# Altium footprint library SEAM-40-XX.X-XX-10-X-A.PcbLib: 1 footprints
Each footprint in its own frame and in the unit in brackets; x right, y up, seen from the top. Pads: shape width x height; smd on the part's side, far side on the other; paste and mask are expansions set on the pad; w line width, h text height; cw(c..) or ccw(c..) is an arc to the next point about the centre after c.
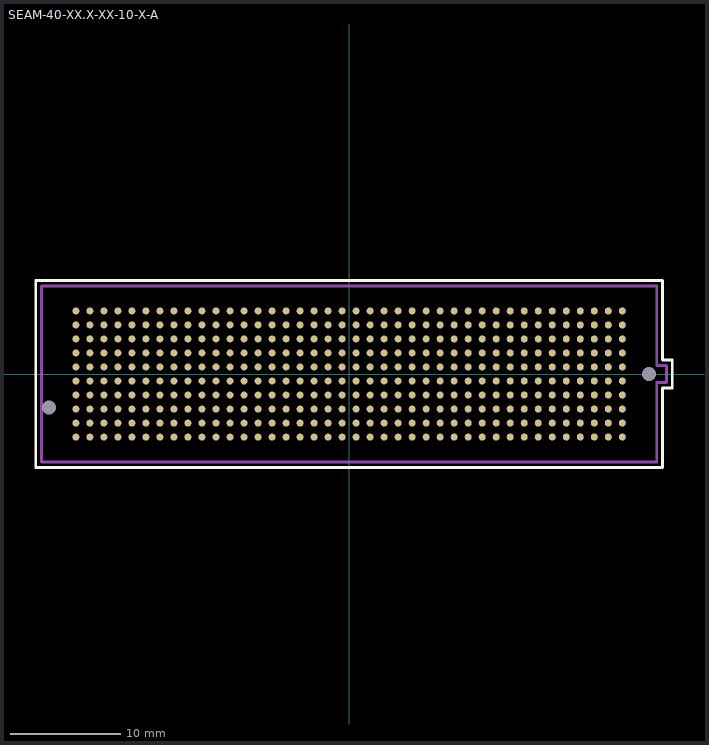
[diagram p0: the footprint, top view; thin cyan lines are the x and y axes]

## SEAM-40-XX.X-XX-10-X-A [mil]
pads (402):
  round 25 smd paste+5 mask+2: 1(975,225) 2(975,175) 3(975,125) 4(975,75) 5(975,25) 6(975,-25) 7(975,-75) 8(975,-125) 9(975,-175) 10(975,-225) 11(925,225) 12(925,175) 13(925,125) 14(925,75) 15(925,25) 16(925,-25) 17(925,-75) 18(925,-125) 19(925,-175) 20(925,-225) 21(875,225) 22(875,175) 23(875,125) 24(875,75) 25(875,25) 26(875,-25) 27(875,-75) 28(875,-125) 29(875,-175) 30(875,-225) 31(825,225) 32(825,175) 33(825,125) 34(825,75) 35(825,25) 36(825,-25) 37(825,-75) 38(825,-125) 39(825,-175) 40(825,-225) 41(775,225) 42(775,175) 43(775,125) 44(775,75) 45(775,25) 46(775,-25) 47(775,-75) 48(775,-125) 49(775,-175) 50(775,-225) 51(725,225) 52(725,175) 53(725,125) 54(725,75) 55(725,25) 56(725,-25) 57(725,-75) 58(725,-125) 59(725,-175) 60(725,-225) 61(675,225) 62(675,175) 63(675,125) 64(675,75) 65(675,25) 66(675,-25) 67(675,-75) 68(675,-125) 69(675,-175) 70(675,-225) 71(625,225) 72(625,175) 73(625,125) 74(625,75) 75(625,25) 76(625,-25) 77(625,-75) 78(625,-125) 79(625,-175) 80(625,-225) 81(575,225) 82(575,175) 83(575,125) 84(575,75) 85(575,25) 86(575,-25) 87(575,-75) 88(575,-125) 89(575,-175) 90(575,-225) 91(525,225) 92(525,175) 93(525,125) 94(525,75) 95(525,25) 96(525,-25) 97(525,-75) 98(525,-125) 99(525,-175) 100(525,-225) 101(475,225) 102(475,175) 103(475,125) 104(475,75) 105(475,25) 106(475,-25) 107(475,-75) 108(475,-125) 109(475,-175) 110(475,-225) 111(425,225) 112(425,175) 113(425,125) 114(425,75) 115(425,25) 116(425,-25) 117(425,-75) 118(425,-125) 119(425,-175) 120(425,-225) 121(375,225) 122(375,175) 123(375,125) 124(375,75) 125(375,25) 126(375,-25) 127(375,-75) 128(375,-125) 129(375,-175) 130(375,-225) 131(325,225) 132(325,175) 133(325,125) 134(325,75) 135(325,25) 136(325,-25) 137(325,-75) 138(325,-125) 139(325,-175) 140(325,-225) 141(275,225) 142(275,175) 143(275,125) 144(275,75) 145(275,25) 146(275,-25) 147(275,-75) 148(275,-125) 149(275,-175) 150(275,-225) 151(225,225) 152(225,175) 153(225,125) 154(225,75) 155(225,25) 156(225,-25) 157(225,-75) 158(225,-125) 159(225,-175) 160(225,-225) 161(175,225) 162(175,175) 163(175,125) 164(175,75) 165(175,25) 166(175,-25) 167(175,-75) 168(175,-125) 169(175,-175) 170(175,-225) 171(125,225) 172(125,175) 173(125,125) 174(125,75) 175(125,25) 176(125,-25) 177(125,-75) 178(125,-125) 179(125,-175) 180(125,-225) 181(75,225) 182(75,175) 183(75,125) 184(75,75) 185(75,25) 186(75,-25) 187(75,-75) 188(75,-125) 189(75,-175) 190(75,-225) 191(25,225) 192(25,175) 193(25,125) 194(25,75) 195(25,25) 196(25,-25) 197(25,-75) 198(25,-125) 199(25,-175) 200(25,-225) 201(-25,225) 202(-25,175) 203(-25,125) 204(-25,75) 205(-25,25) 206(-25,-25) 207(-25,-75) 208(-25,-125) 209(-25,-175) 210(-25,-225) 211(-75,225) 212(-75,175) 213(-75,125) 214(-75,75) 215(-75,25) 216(-75,-25) 217(-75,-75) 218(-75,-125) 219(-75,-175) 220(-75,-225) 221(-125,225) 222(-125,175) 223(-125,125) 224(-125,75) 225(-125,25) 226(-125,-25) 227(-125,-75) 228(-125,-125) 229(-125,-175) 230(-125,-225) 231(-175,225) 232(-175,175) 233(-175,125) 234(-175,75) 235(-175,25) 236(-175,-25) 237(-175,-75) 238(-175,-125) 239(-175,-175) 240(-175,-225) 241(-225,225) 242(-225,175) 243(-225,125) 244(-225,75) 245(-225,25) 246(-225,-25) 247(-225,-75) 248(-225,-125) 249(-225,-175) 250(-225,-225) 251(-275,225) 252(-275,175) 253(-275,125) 254(-275,75) 255(-275,25) 256(-275,-25) 257(-275,-75) 258(-275,-125) 259(-275,-175) 260(-275,-225) 261(-325,225) 262(-325,175) 263(-325,125) 264(-325,75) 265(-325,25) 266(-325,-25) 267(-325,-75) 268(-325,-125) 269(-325,-175) 270(-325,-225) 271(-375,225) 272(-375,175) 273(-375,125) 274(-375,75) 275(-375,25) 276(-375,-25) 277(-375,-75) 278(-375,-125) 279(-375,-175) 280(-375,-225) 281(-425,225) 282(-425,175) 283(-425,125) 284(-425,75) 285(-425,25) 286(-425,-25) 287(-425,-75) 288(-425,-125) 289(-425,-175) 290(-425,-225) 291(-475,225) 292(-475,175) 293(-475,125) 294(-475,75) 295(-475,25) 296(-475,-25) 297(-475,-75) 298(-475,-125) 299(-475,-175) 300(-475,-225) 301(-525,225) 302(-525,175) 303(-525,125) 304(-525,75) 305(-525,25) 306(-525,-25) 307(-525,-75) 308(-525,-125) 309(-525,-175) 310(-525,-225) 311(-575,225) 312(-575,175) 313(-575,125) 314(-575,75) 315(-575,25) 316(-575,-25) 317(-575,-75) 318(-575,-125) 319(-575,-175) 320(-575,-225) 321(-625,225) 322(-625,175) 323(-625,125) 324(-625,75) 325(-625,25) 326(-625,-25) 327(-625,-75) 328(-625,-125) 329(-625,-175) 330(-625,-225) 331(-675,225) 332(-675,175) 333(-675,125) 334(-675,75) 335(-675,25) 336(-675,-25) 337(-675,-75) 338(-675,-125) 339(-675,-175) 340(-675,-225) 341(-725,225) 342(-725,175) 343(-725,125) 344(-725,75) 345(-725,25) 346(-725,-25) 347(-725,-75) 348(-725,-125) 349(-725,-175) 350(-725,-225) 351(-775,225) 352(-775,175) 353(-775,125) 354(-775,75) 355(-775,25) 356(-775,-25) 357(-775,-75) 358(-775,-125) 359(-775,-175) 360(-775,-225) 361(-825,225) 362(-825,175) 363(-825,125) 364(-825,75) 365(-825,25) 366(-825,-25) 367(-825,-75) 368(-825,-125) 369(-825,-175) 370(-825,-225) 371(-875,225) 372(-875,175) 373(-875,125) 374(-875,75) 375(-875,25) 376(-875,-25) 377(-875,-75) 378(-875,-125) 379(-875,-175) 380(-875,-225) 381(-925,225) 382(-925,175) 383(-925,125) 384(-925,75) 385(-925,25) 386(-925,-25) 387(-925,-75) 388(-925,-125) 389(-925,-175) 390(-925,-225) 391(-975,225) 392(-975,175) 393(-975,125) 394(-975,75) 395(-975,25) 396(-975,-25) 397(-975,-75) 398(-975,-125) 399(-975,-175) 400(-975,-225)
  round 0 hole 50 unplated: 401(1070.5,0) 402(-1070.5,-120)
Top Overlay:
  lines w10: -1118,-334 1118,-334 1118,-50 1153,-50 1153,50 1118,50 1118,334 -1118,334 -1118,-334
Mechanical 1:
  lines w10: -1098,-314 1098,-314 1098,-30 1133,-30 1133,30 1098,30 1098,314 -1098,314 -1098,-314
  text "J1" at -17.57,-18 h30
